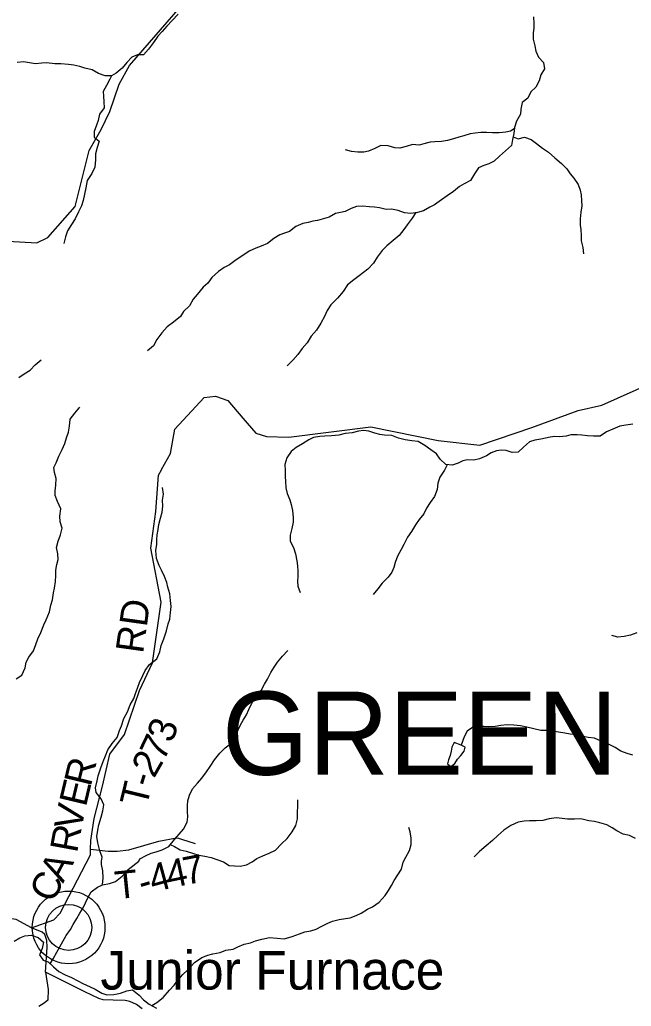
# Model space of a CAD drawing. Extents: x 1624196 to 2029251, y 146837 to 440034.
# Drawn here: x 1879636 to 1886250, y 226226 to 236889 of the extents above; entities that cross this region are included whole.
import ezdxf

# ---------------------------------------------------------------- set-up
doc = ezdxf.new("R2010")
doc.units = 0
for name, color, linetype in [('GM_X_County_Road', 7, 'Continuous'), ('GM_X_Minor_Lake', 7, 'Continuous'), ('GM_X_Minor_River', 7, 'Continuous'), ('GM_X_Township_Road', 7, 'Continuous'), ('GM_X_Township_Road_Text', 7, 'Continuous'), ('GM_X_Township_Text', 7, 'Continuous'), ('GM_X_Unincorporated', 7, 'Continuous'), ('GM_X_Unincorporated_Location', 7, 'Continuous'), ('GM_X_Unincorporated_Text', 7, 'Continuous')]:
    doc.layers.add(name, color=color, linetype=linetype)

msp = doc.modelspace()

# ---------------------------------------------------------------- linework, layer by layer
at = {"layer": 'GM_X_County_Road'}
for points in [[(1879376, 234504), (1879820, 234477), (1879941, 234534), (1880235, 234869), (1880387, 235474), (1880518, 235701), (1880612, 235896), (1880711, 236191), (1880823, 236396), (1881447, 237114)], [(1880961, 226197), (1880899, 226247), (1880827, 226279), (1880776, 226290), (1880646, 226293), (1880537, 226296), (1880492, 226312), (1880339, 226383), (1879914, 226594), (1879933, 226864), (1879929, 226936), (1879908, 227003), (1879879, 227028), (1879763, 227076), (1879597, 227164), (1879371, 227195)]]:
    msp.add_lwpolyline(points, dxfattribs=at)
at = {"layer": 'GM_X_Minor_Lake'}
for points in [[(1884409, 229048), (1884333, 229076), (1884311, 229028), (1884301, 228984), (1884293, 228938), (1884272, 228889), (1884262, 228845), (1884283, 228829)], [(1884283, 228829), (1884298, 228818), (1884340, 228852), (1884370, 228898), (1884408, 228938), (1884441, 228984), (1884455, 229026), (1884409, 229048)]]:
    msp.add_lwpolyline(points, dxfattribs=at)
at = {"layer": 'GM_X_Minor_River'}
for points in [[(1881348, 236948), (1881284, 236881), (1881225, 236819), (1881175, 236763), (1881130, 236712), (1881082, 236644), (1881027, 236570), (1880973, 236511), (1880909, 236511), (1880847, 236484), (1880794, 236426), (1880744, 236366), (1880680, 236311), (1880629, 236283), (1880561, 236282), (1880488, 236308), (1880418, 236349), (1880340, 236367), (1880286, 236382), (1880221, 236398), (1880163, 236405), (1880079, 236413), (1880015, 236414), (1879927, 236423), (1879875, 236419), (1879805, 236411), (1879743, 236424), (1879675, 236434), (1879607, 236425)], [(1885193, 236920), (1885197, 236848), (1885196, 236798), (1885190, 236748), (1885189, 236678), (1885207, 236606), (1885218, 236550), (1885248, 236483), (1885299, 236425), (1885311, 236357), (1885272, 236295), (1885254, 236229), (1885217, 236159), (1885163, 236108), (1885130, 236040), (1885070, 235994), (1885057, 235922), (1885053, 235870), (1885008, 235791), (1884986, 235725), (1884981, 235659), (1884965, 235595), (1884956, 235529), (1884890, 235473), (1884824, 235416), (1884767, 235360), (1884709, 235332), (1884655, 235313), (1884599, 235289), (1884554, 235222), (1884512, 235152), (1884442, 235114), (1884391, 235085), (1884327, 235033), (1884259, 234984), (1884196, 234942), (1884120, 234889), (1884070, 234863), (1884002, 234825), (1883937, 234806), (1883867, 234796), (1883798, 234803), (1883728, 234826), (1883658, 234840), (1883598, 234837), (1883528, 234857), (1883474, 234864), (1883416, 234866), (1883348, 234875), (1883278, 234869), (1883220, 234850), (1883154, 234816), (1883104, 234806), (1883050, 234793), (1882982, 234755), (1882908, 234732), (1882856, 234720), (1882805, 234711), (1882755, 234699), (1882697, 234687), (1882623, 234654), (1882553, 234600), (1882501, 234583), (1882449, 234563), (1882384, 234526), (1882314, 234472), (1882246, 234443), (1882190, 234419), (1882117, 234386), (1882039, 234334), (1881977, 234295), (1881906, 234241), (1881848, 234210), (1881784, 234168), (1881715, 234104), (1881669, 234041), (1881619, 233997), (1881554, 233920), (1881510, 233868), (1881471, 233798), (1881407, 233734), (1881376, 233683), (1881298, 233619), (1881230, 233568), (1881173, 233506), (1881119, 233432), (1881082, 233365), (1881018, 233311)], [(1880627, 236283), (1880611, 236247), (1880573, 236177), (1880538, 236114), (1880540, 236063), (1880547, 236003), (1880549, 235937), (1880500, 235868), (1880484, 235800), (1880467, 235748), (1880441, 235680), (1880442, 235618), (1880494, 235577), (1880473, 235507), (1880455, 235439), (1880454, 235373), (1880448, 235297), (1880417, 235228), (1880365, 235150), (1880350, 235072), (1880337, 235004), (1880321, 234934), (1880304, 234878), (1880272, 234814), (1880235, 234738), (1880197, 234677), (1880152, 234609), (1880132, 234541), (1880113, 234471)], [(1884985, 235711), (1884942, 235685), (1884892, 235673), (1884820, 235668), (1884750, 235668), (1884684, 235671), (1884624, 235671), (1884560, 235664), (1884506, 235656), (1884438, 235635), (1884384, 235619), (1884327, 235602), (1884261, 235584), (1884199, 235573), (1884127, 235569), (1884075, 235564), (1884007, 235546), (1883955, 235535), (1883885, 235539), (1883815, 235520), (1883747, 235502), (1883693, 235505), (1883619, 235525), (1883543, 235530), (1883475, 235496), (1883407, 235469), (1883357, 235459), (1883291, 235456), (1883223, 235464), (1883159, 235481)], [(1884973, 235624), (1885027, 235600), (1885095, 235618), (1885169, 235595), (1885224, 235551), (1885290, 235500), (1885356, 235456), (1885423, 235395), (1885495, 235334), (1885552, 235276), (1885588, 235225), (1885627, 235175), (1885675, 235109), (1885698, 235046), (1885708, 234996), (1885711, 234932), (1885715, 234876), (1885706, 234810), (1885698, 234738), (1885699, 234670), (1885705, 234620), (1885708, 234558), (1885708, 234500), (1885725, 234428), (1885735, 234359)], [(1883921, 234804), (1883879, 234746), (1883826, 234673), (1883790, 234621), (1883740, 234557), (1883675, 234502), (1883607, 234446), (1883556, 234394), (1883502, 234321), (1883461, 234257), (1883399, 234194), (1883306, 234122), (1883248, 234079), (1883182, 234025), (1883133, 233953), (1883073, 233878), (1883002, 233806), (1882962, 233748), (1882931, 233681), (1882891, 233611), (1882846, 233535), (1882788, 233468), (1882745, 233398), (1882689, 233336), (1882642, 233272), (1882588, 233209), (1882529, 233149)], [(1879626, 233023), (1879685, 233063), (1879747, 233101), (1879801, 233158), (1879866, 233214)], [(1879597, 229766), (1879659, 229806), (1879693, 229886), (1879706, 229946), (1879736, 229998), (1879785, 230067), (1879811, 230137), (1879832, 230199), (1879864, 230267), (1879895, 230349), (1879921, 230403), (1879956, 230488), (1879973, 230560), (1879989, 230618), (1880002, 230694), (1880012, 230746), (1880021, 230816), (1880025, 230884), (1880026, 230940), (1880038, 231002), (1880052, 231054), (1880047, 231118), (1880034, 231186), (1880050, 231252), (1880077, 231322), (1880093, 231394), (1880072, 231464), (1880070, 231525), (1880079, 231603), (1880045, 231683), (1880020, 231747), (1880018, 231799), (1880027, 231857), (1880029, 231929), (1880012, 231995), (1880006, 232048), (1880029, 232101), (1880059, 232173), (1880094, 232245), (1880124, 232309), (1880141, 232369), (1880163, 232433), (1880174, 232497), (1880182, 232573), (1880233, 232636), (1880285, 232700)], [(1886266, 232517), (1886190, 232508), (1886126, 232497), (1886051, 232465), (1885983, 232434), (1885913, 232388), (1885843, 232389), (1885775, 232391), (1885715, 232398), (1885663, 232404), (1885597, 232403), (1885545, 232387), (1885475, 232382), (1885423, 232384), (1885373, 232378), (1885323, 232367), (1885273, 232357), (1885207, 232346), (1885151, 232326), (1885085, 232268), (1885028, 232215), (1884960, 232213), (1884898, 232232), (1884843, 232236), (1884791, 232229), (1884736, 232207), (1884684, 232176), (1884610, 232144), (1884546, 232129), (1884480, 232131), (1884428, 232123), (1884378, 232098), (1884314, 232074), (1884246, 232081), (1884182, 232141), (1884145, 232196), (1884081, 232242), (1884016, 232289), (1883944, 232331), (1883876, 232336), (1883804, 232349), (1883732, 232367), (1883661, 232394), (1883581, 232400), (1883529, 232407), (1883477, 232421), (1883411, 232442), (1883353, 232450), (1883299, 232443), (1883231, 232425), (1883157, 232418), (1883087, 232400), (1883007, 232393), (1882937, 232387), (1882883, 232386), (1882813, 232374), (1882761, 232347), (1882693, 232307), (1882626, 232266)], [(1882626, 232266), (1882572, 232222), (1882524, 232154), (1882503, 232082), (1882506, 232016), (1882508, 231950), (1882512, 231900), (1882513, 231828), (1882530, 231768), (1882558, 231700), (1882571, 231649), (1882585, 231583), (1882592, 231509), (1882594, 231459), (1882579, 231391), (1882561, 231317), (1882562, 231253), (1882596, 231185), (1882617, 231117), (1882633, 231042), (1882640, 230988), (1882642, 230928), (1882643, 230870), (1882641, 230820), (1882645, 230768), (1882668, 230700)], [(1884260, 232080), (1884231, 232021), (1884181, 231945), (1884158, 231881), (1884150, 231813), (1884121, 231735), (1884075, 231672), (1884036, 231610), (1884006, 231548), (1883955, 231487), (1883915, 231429), (1883874, 231359), (1883828, 231295), (1883791, 231216), (1883763, 231162), (1883722, 231090), (1883696, 231022), (1883683, 230970), (1883659, 230918), (1883619, 230865), (1883556, 230801), (1883510, 230739), (1883457, 230678)], [(1880521, 227796), (1880527, 227837), (1880503, 227908), (1880482, 227994), (1880471, 228062), (1880479, 228128), (1880492, 228186), (1880518, 228272), (1880535, 228338), (1880547, 228404), (1880516, 228470), (1880462, 228537), (1880457, 228589), (1880473, 228663), (1880484, 228717), (1880512, 228802), (1880537, 228872), (1880563, 228932), (1880590, 228998), (1880634, 229066), (1880691, 229133), (1880715, 229207), (1880736, 229259), (1880762, 229335), (1880803, 229409), (1880832, 229483), (1880870, 229554), (1880889, 229608), (1880911, 229666), (1880931, 229724), (1880968, 229802), (1880992, 229854), (1881041, 229922), (1881119, 229981), (1881150, 230057), (1881166, 230125), (1881193, 230199), (1881224, 230284), (1881242, 230360), (1881261, 230412), (1881265, 230482), (1881272, 230548), (1881266, 230612), (1881259, 230683), (1881239, 230757), (1881226, 230807), (1881200, 230873), (1881169, 230940), (1881145, 230990), (1881114, 231066), (1881107, 231152), (1881119, 231222), (1881119, 231272), (1881124, 231322), (1881134, 231380), (1881139, 231434), (1881157, 231502), (1881176, 231566), (1881182, 231630), (1881181, 231698), (1881191, 231762), (1881180, 231832)], [(1886310, 230261), (1886240, 230239), (1886174, 230224), (1886104, 230217), (1886038, 230233)], [(1880924, 227794), (1880934, 227820), (1881005, 227856), (1881059, 227881), (1881111, 227897), (1881177, 227919), (1881247, 227954), (1881310, 228028), (1881360, 228085), (1881407, 228141), (1881447, 228217), (1881454, 228273), (1881450, 228333), (1881451, 228395), (1881453, 228447), (1881471, 228507), (1881504, 228577), (1881560, 228638), (1881607, 228692), (1881655, 228760), (1881694, 228819), (1881744, 228889), (1881799, 228963), (1881857, 229018), (1881920, 229068), (1881966, 229142), (1881999, 229213), (1882025, 229267), (1882053, 229319), (1882090, 229377), (1882112, 229433), (1882147, 229501), (1882189, 229570), (1882246, 229640), (1882282, 229708), (1882317, 229760), (1882353, 229833), (1882388, 229891), (1882422, 229945), (1882477, 230009), (1882535, 230072)], [(1886266, 228942), (1886206, 228960), (1886136, 228985), (1886074, 229024), (1886003, 229060), (1885923, 229093), (1885853, 229123), (1885783, 229132), (1885730, 229142), (1885664, 229159), (1885588, 229168), (1885530, 229178), (1885462, 229189), (1885394, 229201), (1885334, 229208), (1885272, 229208), (1885195, 229225), (1885119, 229243), (1885053, 229256), (1884979, 229264), (1884909, 229267), (1884839, 229261), (1884777, 229252), (1884707, 229248), (1884655, 229251), (1884599, 229251), (1884533, 229238), (1884475, 229200), (1884442, 229138), (1884409, 229048)], [(1882151, 227787), (1882200, 227823), (1882266, 227852), (1882334, 227880), (1882402, 227915), (1882467, 227983), (1882529, 228038), (1882584, 228110), (1882622, 228180), (1882641, 228252), (1882639, 228322), (1882642, 228394), (1882644, 228458)], [(1886294, 228041), (1886231, 228073), (1886163, 228086), (1886095, 228123), (1886042, 228155), (1885986, 228187), (1885910, 228210), (1885854, 228223), (1885790, 228229), (1885705, 228252), (1885635, 228250), (1885559, 228249), (1885501, 228255), (1885439, 228264), (1885363, 228252), (1885295, 228235), (1885221, 228231), (1885151, 228230), (1885091, 228228), (1885027, 228215), (1884946, 228180), (1884872, 228130), (1884806, 228071), (1884749, 228017), (1884679, 227961), (1884607, 227900), (1884550, 227842)], [(1883784, 227785), (1883813, 227838), (1883853, 227910), (1883870, 227976), (1883870, 228044), (1883859, 228110), (1883843, 228160)], [(1881264, 227974), (1881309, 227952), (1881371, 227919), (1881435, 227903), (1881503, 227882), (1881572, 227861), (1881638, 227849), (1881706, 227834), (1881840, 227787)], [(1879964, 226686), (1879998, 226740), (1880036, 226812), (1880087, 226900), (1880139, 226992), (1880184, 227058), (1880212, 227110), (1880252, 227174), (1880287, 227231), (1880321, 227291), (1880374, 227399), (1880410, 227465), (1880476, 227513), (1880532, 227540), (1880608, 227554), (1880672, 227576), (1880744, 227633), (1880809, 227705), (1880924, 227794)], [(1880532, 227540), (1880538, 227616), (1880536, 227690), (1880521, 227757), (1880521, 227796)], [(1881065, 226234), (1881119, 226267), (1881188, 226323), (1881256, 226401), (1881306, 226454), (1881349, 226512), (1881401, 226570), (1881451, 226616), (1881525, 226699), (1881604, 226753), (1881670, 226779), (1881724, 226792), (1881802, 226806), (1881864, 226832), (1881946, 226845), (1881996, 226869), (1882062, 226897), (1882130, 226912), (1882184, 226932), (1882256, 226951), (1882338, 226971), (1882420, 226963), (1882495, 226954), (1882581, 226980), (1882661, 227009), (1882721, 227031), (1882783, 227042), (1882843, 227060), (1882904, 227092), (1882968, 227125), (1883020, 227145), (1883090, 227165), (1883158, 227176), (1883210, 227184), (1883276, 227206), (1883328, 227233), (1883396, 227277), (1883452, 227301), (1883522, 227352), (1883590, 227422), (1883623, 227478), (1883655, 227530), (1883687, 227584), (1883726, 227648), (1883764, 227710), (1883784, 227785)], [(1881840, 227787), (1881901, 227747), (1881957, 227746), (1882021, 227742), (1882089, 227754), (1882151, 227787)], [(1879574, 226931), (1879638, 226965), (1879692, 226989), (1879764, 226994), (1879836, 226970), (1879893, 226921), (1879877, 226851), (1879851, 226781), (1879890, 226723), (1879942, 226705), (1880000, 226654), (1880059, 226602), (1880127, 226567), (1880197, 226539), (1880264, 226503), (1880320, 226474), (1880396, 226438), (1880451, 226413), (1880525, 226369), (1880579, 226351), (1880653, 226352), (1880725, 226368), (1880793, 226393), (1880857, 226405), (1880926, 226346), (1880974, 226296), (1881037, 226250), (1881115, 226207)]]:
    msp.add_lwpolyline(points, dxfattribs=at)
at = {"layer": 'GM_X_Township_Road'}
for points in [[(1882049, 232584), (1882189, 232421), (1882306, 232386), (1882546, 232376), (1883434, 232490), (1884161, 232343), (1884613, 232290), (1885176, 232480), (1885676, 232667), (1885931, 232724), (1886474, 232965), (1887278, 233543), (1887601, 233730)], [(1881170, 232026), (1881170, 232027), (1881268, 232199), (1881312, 232465), (1881630, 232807), (1881752, 232822), (1881886, 232775), (1882049, 232584), (1882049, 232584)], [(1879763, 227076), (1880005, 227159), (1880073, 227234), (1880401, 227865), (1880402, 227925), (1880403, 228017), (1880441, 228257), (1880531, 228604), (1880611, 228950), (1880769, 229162), (1880932, 229641), (1881072, 229940), (1881165, 230595), (1881053, 231178), (1881107, 231574), (1881137, 231968), (1881170, 232026)], [(1880402, 227925), (1880592, 227903), (1880689, 227904), (1880814, 227917), (1881141, 228012), (1881330, 228048), (1881353, 228045), (1881387, 228031), (1881533, 227984)], [(1879914, 226594), (1879942, 226408), (1879939, 226293), (1879901, 226259), (1879841, 226224)]]:
    msp.add_lwpolyline(points, dxfattribs=at)
at = {"layer": 'GM_X_Unincorporated'}
for radius in [393, 249]:
    msp.add_circle((1880165, 227079), radius, dxfattribs=at)
at = {"layer": 'GM_X_Unincorporated_Location'}
msp.add_line((1880165, 227079), (1880165, 227079), dxfattribs=at)

# ---------------------------------------------------------------- texts
at = {"layer": 'GM_X_Township_Road_Text'}
for s, rotation, p in [('RD', 82.0779, (1880969, 230031)), ('3', 70.6363, (1881285, 229063)), ('7', 64.2924, (1881191, 228863)), ('2', 60.1738, (1881088, 228682)), ('R', 76.4318, (1880403, 228591)), ('-', 73.0252, (1881059, 228581)), ('E', 76.6014, (1880351, 228373)), ('T', 76.2797, (1881007, 228367)), ('V', 78.8412, (1880300, 228117)), ('R', 79.6474, (1880256, 227876)), ('7', 10.8073, (1881432, 227537)), ('A', 62.6668, (1880104, 227550)), ('4', 15.2366, (1881079, 227452)), ('4', 11.9457, (1881253, 227499)), ('C', 63.9228, (1879996, 227330)), ('T', 5.8624, (1880680, 227383)), ('-', 16.4249, (1880962, 227417))]:
    msp.add_text(s, height=300, rotation=rotation, dxfattribs=at).set_placement(p)
at = {"layer": 'GM_X_Township_Text'}
msp.add_text('GREEN', height=900, rotation=0, dxfattribs=at).set_placement((1881823, 228728))
at = {"layer": 'GM_X_Unincorporated_Text'}
msp.add_text('Junior Furnace', height=417, rotation=0, dxfattribs=at).set_placement((1880509, 226407))

doc.saveas('drawing.dxf')
